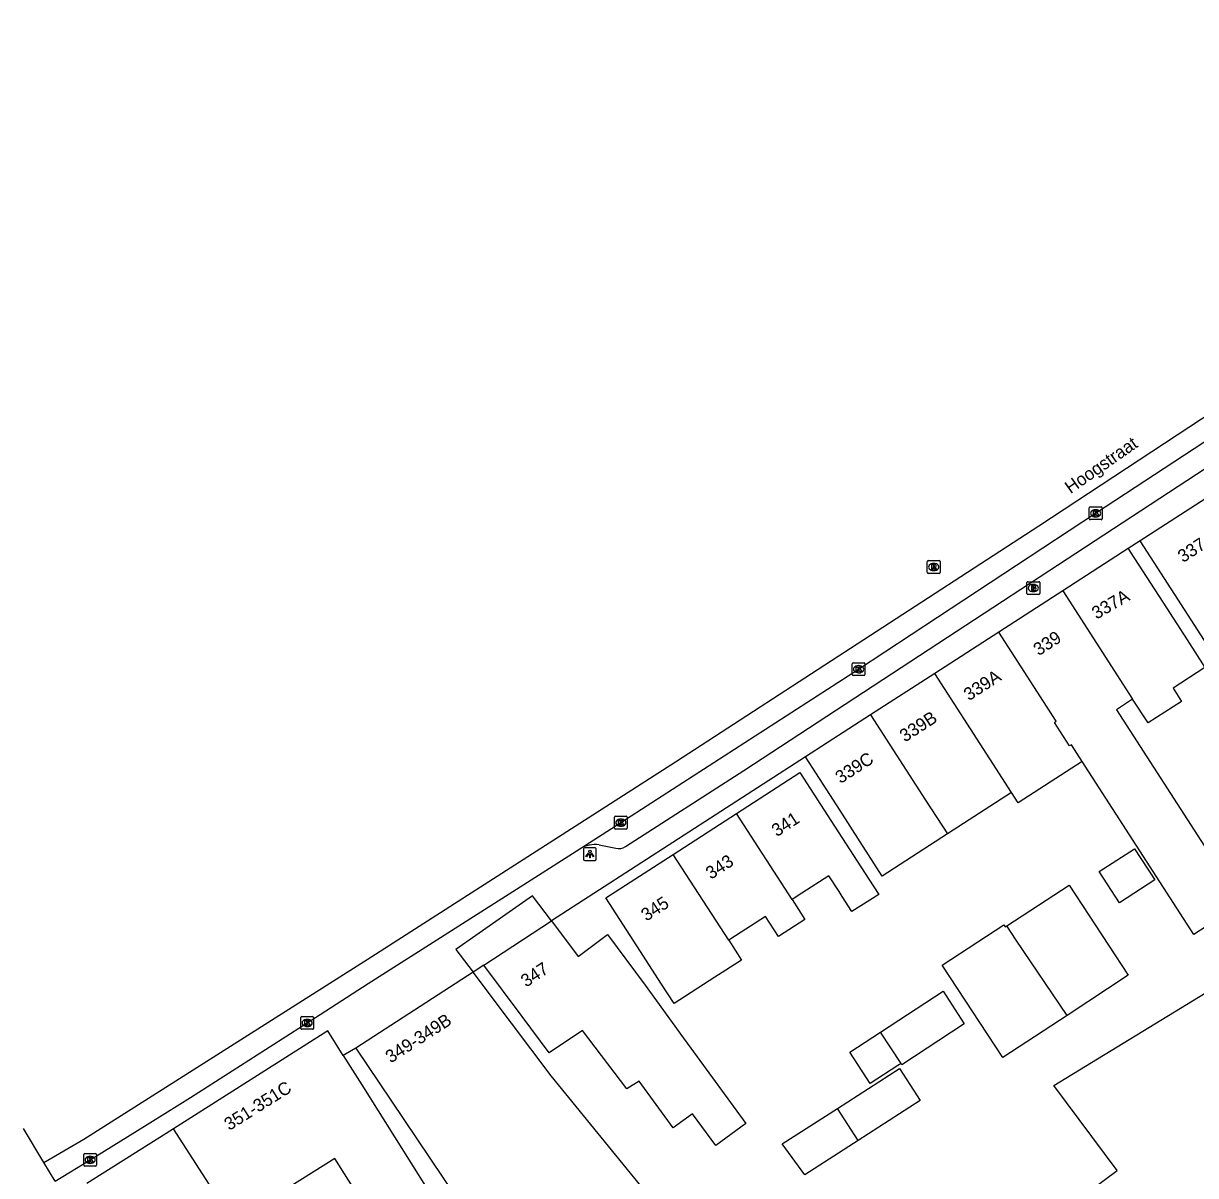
# Model space of a CAD drawing. Extents: x 159822 to 160765, y 380693 to 381634.
# Drawn here: x 160002.9 to 160094.7, y 381523.9 to 381614.2 of the extents above; entities that cross this region are included whole.
import ezdxf

# ---------------------------------------------------------------- set-up
doc = ezdxf.new("R2010")
doc.units = 0
for name, color, linetype in [('IMGEO_Brandkraan', 7, 'Continuous'), ('IMGEO_Erf', 7, 'Continuous'), ('IMGEO_Kolk', 7, 'Continuous'), ('IMGEO_Lichtpunt', 7, 'Continuous'), ('IMGEO_Openbare_ruimte_label', 7, 'Continuous'), ('IMGEO_Pand', 7, 'Continuous'), ('IMGEO_Pand_nummerreeks', 7, 'Continuous'), ('IMGEO_Rijbaan_lokaal_gesloten', 7, 'Continuous'), ('IMGEO_Rioolput', 7, 'Continuous'), ('IMGEO_Voetpad_open', 7, 'Continuous')]:
    doc.layers.add(name, color=color, linetype=linetype)

msp = doc.modelspace()

# ---------------------------------------------------------------- linework, layer by layer
at = {"layer": 'IMGEO_Brandkraan'}
for p, q in [((160081.484, 381569.508), (160081.484, 381570.36)), ((160081.559, 381570.434), (160082.411, 381570.434)), ((160081.972, 381570.214), (160081.997, 381570.214)), ((160082.485, 381570.36), (160082.485, 381569.508)), ((160082.411, 381569.434), (160081.559, 381569.434)), ((160081.995, 381569.654), (160081.97, 381569.654))]:
    msp.add_line(p, q, dxfattribs=at)
for points in [[(160081.484, 381569.508), (160081.484, 381570.36)], [(160081.559, 381570.434), (160082.411, 381570.434)], [(160081.832, 381570.134), (160081.832, 381569.734), (160082.045, 381569.734)], [(160082.063, 381570.134), (160081.832, 381570.134)], [(160082.011, 381570.053), (160081.957, 381570.053), (160081.957, 381569.977)], [(160081.957, 381569.977), (160082.01, 381569.977)], [(160082.019, 381569.901), (160081.957, 381569.901), (160081.957, 381569.82)], [(160081.957, 381569.82), (160082.019, 381569.82)], [(160082.485, 381570.36), (160082.485, 381569.508)], [(160082.411, 381569.434), (160081.559, 381569.434)]]:
    msp.add_lwpolyline(points, dxfattribs=at)
for centre, radius, start, end in [((160081.561, 381570.358), 0.0765, 91.55205, 178.44795), ((160081.561, 381570.358), 0.0765, 91.55205, 178.44795), ((160082.012, 381570.015), 0.0379, 267.82845, 90.93552), ((160082.02, 381569.86), 0.0404, 269.87594, 90.50774), ((160082.067, 381569.989), 0.145, 59.4692, 91.53667), ((160082.092, 381570.036), 0.0922, 285.51372, 58.15012), ((160082.097, 381569.844), 0.105, 301.31148, 78.98903), ((160082.409, 381570.358), 0.0765, 1.55205, 88.44795), ((160082.409, 381570.358), 0.0765, 1.55205, 88.44795), ((160081.561, 381569.51), 0.0765, 181.55205, 268.44795), ((160081.561, 381569.51), 0.0765, 181.55205, 268.44795), ((160082.051, 381569.985), 0.251, 268.66757, 293.53466), ((160082.409, 381569.51), 0.0765, 271.55205, 358.44795), ((160082.409, 381569.51), 0.0765, 271.55205, 358.44795)]:
    msp.add_arc(centre, radius, start, end, dxfattribs=at)
for centre, major_axis, ratio, start_param, end_param in [((160081.971, 381569.934), (-0.387, 0.002), 0.722429, 4.712389, 7.853982), ((160081.996, 381569.934), (-0.39, 0.002), 0.717154, 1.570796, 4.712389)]:
    msp.add_ellipse(centre, major_axis=major_axis, ratio=ratio, start_param=start_param, end_param=end_param, dxfattribs=at)
at = {"layer": 'IMGEO_Erf'}
msp.add_lwpolyline([(160038.953, 381540.37), (160038.115, 381539.825)], dxfattribs=at)
at = {"layer": 'IMGEO_Kolk'}
for p, q in [((160086.447, 381576.297), (160087.299, 381576.297)), ((160086.372, 381575.371), (160086.372, 381576.223)), ((160086.883, 381575.517), (160086.858, 381575.517)), ((160086.86, 381576.077), (160086.885, 381576.077)), ((160087.373, 381576.223), (160087.373, 381575.371)), ((160087.299, 381575.297), (160086.447, 381575.297)), ((160067.799, 381563.149), (160067.799, 381564.001)), ((160067.874, 381564.075), (160068.726, 381564.075)), ((160068.287, 381563.855), (160068.312, 381563.855)), ((160068.8, 381564.001), (160068.8, 381563.149)), ((160068.726, 381563.075), (160067.874, 381563.075)), ((160068.31, 381563.295), (160068.285, 381563.295)), ((160049.175, 381551.125), (160049.175, 381551.977)), ((160049.25, 381552.051), (160050.102, 381552.051)), ((160049.663, 381551.831), (160049.688, 381551.831)), ((160050.176, 381551.977), (160050.176, 381551.125)), ((160050.102, 381551.051), (160049.25, 381551.051)), ((160049.686, 381551.271), (160049.661, 381551.271)), ((160024.598, 381535.428), (160024.598, 381536.28)), ((160024.673, 381536.354), (160025.525, 381536.354)), ((160025.086, 381536.134), (160025.111, 381536.134)), ((160025.599, 381536.28), (160025.599, 381535.428)), ((160025.525, 381535.354), (160024.673, 381535.354)), ((160025.109, 381535.574), (160025.084, 381535.574)), ((160007.597, 381524.697), (160007.597, 381525.549)), ((160007.672, 381525.623), (160008.524, 381525.623)), ((160008.108, 381524.843), (160008.083, 381524.843)), ((160008.085, 381525.403), (160008.11, 381525.403)), ((160008.598, 381525.549), (160008.598, 381524.697)), ((160008.524, 381524.623), (160007.672, 381524.623))]:
    msp.add_line(p, q, dxfattribs=at)
for points in [[(160086.447, 381576.297), (160087.299, 381576.297)], [(160086.372, 381575.371), (160086.372, 381576.223)], [(160086.693, 381575.997), (160086.816, 381575.997), (160086.816, 381575.846), (160086.946, 381575.997), (160087.11, 381575.997), (160086.964, 381575.846), (160087.117, 381575.597), (160086.965, 381575.597), (160086.88, 381575.761), (160086.816, 381575.694), (160086.816, 381575.597), (160086.693, 381575.597), (160086.693, 381575.997)], [(160087.373, 381576.223), (160087.373, 381575.371)], [(160087.299, 381575.297), (160086.447, 381575.297)], [(160067.799, 381563.149), (160067.799, 381564.001)], [(160067.874, 381564.075), (160068.726, 381564.075)], [(160068.12, 381563.775), (160068.243, 381563.775), (160068.243, 381563.624), (160068.373, 381563.775), (160068.537, 381563.775), (160068.391, 381563.624), (160068.544, 381563.375), (160068.392, 381563.375), (160068.307, 381563.539), (160068.243, 381563.472), (160068.243, 381563.375), (160068.12, 381563.375), (160068.12, 381563.775)], [(160068.8, 381564.001), (160068.8, 381563.149)], [(160068.726, 381563.075), (160067.874, 381563.075)], [(160049.175, 381551.125), (160049.175, 381551.977)], [(160049.25, 381552.051), (160050.102, 381552.051)], [(160049.496, 381551.751), (160049.619, 381551.751), (160049.619, 381551.6), (160049.749, 381551.751), (160049.913, 381551.751), (160049.767, 381551.6), (160049.92, 381551.351), (160049.768, 381551.351), (160049.683, 381551.515), (160049.619, 381551.448), (160049.619, 381551.351), (160049.496, 381551.351), (160049.496, 381551.751)], [(160050.176, 381551.977), (160050.176, 381551.125)], [(160050.102, 381551.051), (160049.25, 381551.051)], [(160024.598, 381535.428), (160024.598, 381536.28)], [(160024.673, 381536.354), (160025.525, 381536.354)], [(160024.919, 381536.054), (160025.042, 381536.054), (160025.042, 381535.903), (160025.172, 381536.054), (160025.336, 381536.054), (160025.19, 381535.903), (160025.343, 381535.654), (160025.191, 381535.654), (160025.106, 381535.818), (160025.042, 381535.751), (160025.042, 381535.654), (160024.919, 381535.654), (160024.919, 381536.054)], [(160025.599, 381536.28), (160025.599, 381535.428)], [(160025.525, 381535.354), (160024.673, 381535.354)], [(160007.597, 381524.697), (160007.597, 381525.549)], [(160007.672, 381525.623), (160008.524, 381525.623)], [(160007.918, 381525.323), (160008.041, 381525.323), (160008.041, 381525.172), (160008.171, 381525.323), (160008.335, 381525.323), (160008.189, 381525.172), (160008.342, 381524.923), (160008.19, 381524.923), (160008.105, 381525.087), (160008.041, 381525.02), (160008.041, 381524.923), (160007.918, 381524.923), (160007.918, 381525.323)], [(160008.598, 381525.549), (160008.598, 381524.697)], [(160008.524, 381524.623), (160007.672, 381524.623)]]:
    msp.add_lwpolyline(points, dxfattribs=at)
for centre, start, end in [((160086.449, 381576.221), 91.55205, 178.44795), ((160086.449, 381576.221), 91.55205, 178.44795), ((160087.297, 381576.221), 1.55205, 88.44795), ((160087.297, 381576.221), 1.55205, 88.44795), ((160086.449, 381575.373), 181.55205, 268.44795), ((160086.449, 381575.373), 181.55205, 268.44795), ((160087.297, 381575.373), 271.55205, 358.44795), ((160087.297, 381575.373), 271.55205, 358.44795), ((160067.876, 381563.999), 91.55205, 178.44795), ((160067.876, 381563.999), 91.55205, 178.44795), ((160068.724, 381563.999), 1.55205, 88.44795), ((160068.724, 381563.999), 1.55205, 88.44795), ((160067.876, 381563.151), 181.55205, 268.44795), ((160067.876, 381563.151), 181.55205, 268.44795), ((160068.724, 381563.151), 271.55205, 358.44795), ((160068.724, 381563.151), 271.55205, 358.44795), ((160049.252, 381551.975), 91.55205, 178.44795), ((160049.252, 381551.975), 91.55205, 178.44795), ((160050.1, 381551.975), 1.55205, 88.44795), ((160050.1, 381551.975), 1.55205, 88.44795), ((160049.252, 381551.127), 181.55205, 268.44795), ((160049.252, 381551.127), 181.55205, 268.44795), ((160050.1, 381551.127), 271.55205, 358.44795), ((160050.1, 381551.127), 271.55205, 358.44795), ((160024.675, 381536.278), 91.55205, 178.44795), ((160024.675, 381536.278), 91.55205, 178.44795), ((160025.523, 381536.278), 1.55205, 88.44795), ((160025.523, 381536.278), 1.55205, 88.44795), ((160024.675, 381535.43), 181.55205, 268.44795), ((160024.675, 381535.43), 181.55205, 268.44795), ((160025.523, 381535.43), 271.55205, 358.44795), ((160025.523, 381535.43), 271.55205, 358.44795), ((160007.674, 381525.547), 91.55205, 178.44795), ((160007.674, 381525.547), 91.55205, 178.44795), ((160008.522, 381525.547), 1.55205, 88.44795), ((160008.522, 381525.547), 1.55205, 88.44795), ((160007.674, 381524.699), 181.55205, 268.44795), ((160007.674, 381524.699), 181.55205, 268.44795), ((160008.522, 381524.699), 271.55205, 358.44795), ((160008.522, 381524.699), 271.55205, 358.44795)]:
    msp.add_arc(centre, 0.0765, start, end, dxfattribs=at)
for centre, major_axis, ratio, start_param, end_param in [((160086.859, 381575.797), (-0.387, 0.002), 0.722429, 4.712389, 7.853982), ((160086.884, 381575.797), (-0.39, 0.002), 0.717154, 1.570796, 4.712389), ((160068.286, 381563.575), (-0.387, 0.002), 0.722429, 4.712389, 7.853982), ((160068.311, 381563.575), (-0.39, 0.002), 0.717154, 1.570796, 4.712389), ((160049.662, 381551.551), (-0.387, 0.002), 0.722429, 4.712389, 7.853982), ((160049.687, 381551.551), (-0.39, 0.002), 0.717154, 1.570796, 4.712389), ((160025.085, 381535.854), (-0.387, 0.002), 0.722429, 4.712389, 7.853982), ((160025.11, 381535.854), (-0.39, 0.002), 0.717154, 1.570796, 4.712389), ((160008.084, 381525.123), (-0.387, 0.002), 0.722429, 4.712389, 7.853982), ((160008.109, 381525.123), (-0.39, 0.002), 0.717154, 1.570796, 4.712389)]:
    msp.add_ellipse(centre, major_axis=major_axis, ratio=ratio, start_param=start_param, end_param=end_param, dxfattribs=at)
at = {"layer": 'IMGEO_Lichtpunt'}
for p, q in [((160046.756, 381549.491), (160046.756, 381548.684)), ((160046.756, 381549.491), (160046.756, 381548.684)), ((160047.658, 381549.586), (160046.85, 381549.586)), ((160047.658, 381549.586), (160046.85, 381549.586)), ((160047.752, 381548.684), (160047.752, 381549.491)), ((160047.752, 381548.684), (160047.752, 381549.491)), ((160046.85, 381548.59), (160047.658, 381548.59)), ((160046.85, 381548.59), (160047.658, 381548.59))]:
    msp.add_line(p, q, dxfattribs=at)
for points in [[(160047.13, 381549.155), (160047.169, 381549.127), (160046.981, 381548.865), (160046.943, 381548.892), (160047.13, 381549.155)], [(160047.232, 381549.107), (160047.279, 381549.107), (160047.279, 381548.785), (160047.232, 381548.785), (160047.232, 381549.107)], [(160047.342, 381549.127), (160047.38, 381549.154), (160047.567, 381548.892), (160047.528, 381548.864), (160047.342, 381549.127)]]:
    msp.add_lwpolyline(points, dxfattribs=at)
msp.add_circle((160047.255, 381549.289), 0.0994, dxfattribs=at)
for centre, start, end in [((160046.85, 381549.491), 90, 180), ((160046.85, 381549.491), 90, 180), ((160046.85, 381548.684), 180, 270), ((160046.85, 381548.684), 180, 270), ((160047.658, 381549.491), 0, 90), ((160047.658, 381549.491), 0, 90), ((160047.658, 381548.684), 270, 0), ((160047.658, 381548.684), 270, 360)]:
    msp.add_arc(centre, 0.0946, start, end, dxfattribs=at)
at = {"layer": 'IMGEO_Pand'}
for points in [[(160095.508, 381576.952), (160090.358, 381573.626)], [(160111.401, 381551.466), (160106.639, 381548.393), (160093.069, 381569.425), (160090.358, 381573.626)], [(160089.426, 381573.024), (160084.293, 381569.71)], [(160089.426, 381573.024), (160089.58, 381572.786), (160092.139, 381568.82), (160094.029, 381565.891), (160095.435, 381563.711), (160092.933, 381562.096), (160093.607, 381561.052), (160090.99, 381559.363), (160089.77, 381561.223)], [(160084.293, 381569.71), (160079.277, 381566.473)], [(160084.293, 381569.71), (160089.77, 381561.223)], [(160079.277, 381566.473), (160074.26, 381563.234)], [(160085.817, 381556.338), (160084.969, 381557.652), (160084.834, 381557.564), (160083.644, 381559.407), (160083.78, 381559.495), (160079.277, 381566.473)], [(160074.26, 381563.234), (160069.245, 381559.997)], [(160080.28, 381553.904), (160078.579, 381556.541), (160074.26, 381563.234)], [(160089.77, 381561.223), (160088.494, 381560.4), (160098.296, 381545.21), (160094.556, 381542.797), (160085.817, 381556.338)], [(160069.245, 381559.997), (160064.133, 381556.697)], [(160069.245, 381559.997), (160073.551, 381553.324), (160075.265, 381550.666)], [(160075.265, 381550.666), (160070.155, 381547.367), (160068.423, 381550.05), (160066.845, 381552.496), (160064.133, 381556.697)], [(160085.817, 381556.338), (160080.8, 381553.099), (160080.28, 381553.904)], [(160058.738, 381552.271), (160063.706, 381555.488), (160066.417, 381551.287), (160069.104, 381547.123), (160069.874, 381545.93), (160067.781, 381544.579), (160067.011, 381545.772), (160066.772, 381546.143), (160065.968, 381547.388), (160063.846, 381546.019), (160063.182, 381545.591), (160063.088, 381545.53)], [(160080.28, 381553.904), (160075.265, 381550.666)], [(160053.785, 381549.064), (160058.738, 381552.271)], [(160063.088, 381545.53), (160058.738, 381552.271)], [(160058.124, 381542.342), (160059.129, 381540.785), (160057.044, 381539.44), (160053.848, 381537.377), (160052.819, 381538.971), (160051.221, 381541.447), (160048.51, 381545.648), (160053.785, 381549.064)], [(160058.124, 381542.342), (160053.785, 381549.064)], [(160087.155, 381547.723), (160089.916, 381549.505), (160091.496, 381547.056), (160088.735, 381545.274), (160087.155, 381547.723)], [(160079.918, 381543.458), (160084.79, 381546.655), (160089.429, 381539.588), (160084.634, 381536.441)], [(160063.088, 381545.53), (160064.097, 381543.967), (160062.026, 381542.63), (160061.01, 381544.205), (160058.291, 381542.45), (160058.124, 381542.342)], [(160044.254, 381543.855), (160046.328, 381541.069), (160048.636, 381542.793), (160051.59, 381538.802), (160054.594, 381534.655), (160055.146, 381533.881), (160059.463, 381527.971), (160057.11, 381526.252), (160055.3, 381528.73), (160053.782, 381527.621), (160051.102, 381531.29), (160050.142, 381530.675), (160046.669, 381535.268), (160044.068, 381533.505), (160041.94, 381536.361), (160038.953, 381540.37)], [(160038.953, 381540.37), (160044.254, 381543.855)], [(160084.634, 381536.441), (160079.609, 381533.144), (160074.858, 381540.383), (160079.681, 381543.549), (160079.794, 381543.377), (160079.918, 381543.458)], [(160084.634, 381536.441), (160080.647, 381542.328), (160079.918, 381543.458)], [(160110.69, 381494.11), (160105.284, 381501.642), (160102.69, 381505.019), (160102.11, 381505.796), (160097.351, 381512.166), (160089.073, 381505.982), (160080.102, 381517.993), (160088.554, 381524.298), (160083.587, 381530.947), (160101.421, 381541.836)], [(160038.115, 381539.825), (160028.91, 381533.878)], [(160028.91, 381533.878), (160031.703, 381529.731), (160036.757, 381522.228), (160037.103, 381522.461), (160046.627, 381508.396), (160053.016, 381512.481), (160052.51, 381513.232), (160056.874, 381516.17), (160044.202, 381531.699), (160041.112, 381535.824), (160038.115, 381539.825)], [(160070.013, 381535.137), (160074.917, 381538.355), (160076.58, 381535.783), (160071.694, 381532.576), (160071.63, 381532.673)], [(160027.93, 381533.3), (160026.718, 381535.224), (160014.641, 381527.565)], [(160071.63, 381532.673), (160071.373, 381532.507), (160069.208, 381531.113), (160067.604, 381533.556), (160070.013, 381535.137)], [(160071.63, 381532.673), (160070.013, 381535.137)], [(160027.93, 381533.3), (160029.382, 381530.994), (160035.788, 381520.822), (160031.683, 381518.237), (160027.275, 381525.235), (160021.998, 381521.911), (160024.38, 381518.196), (160025.929, 381519.252), (160036.236, 381503.697), (160034.773, 381502.7)], [(160066.636, 381529.156), (160071.51, 381532.294), (160073.13, 381529.778), (160068.26, 381526.642)], [(160068.26, 381526.642), (160064.076, 381523.949), (160062.322, 381526.379), (160066.636, 381529.156)], [(160068.26, 381526.642), (160066.636, 381529.156)], [(160014.641, 381527.565), (160014.041, 381527.185), (160007.851, 381523.273)], [(160019.688, 381519.696), (160014.641, 381527.565)]]:
    msp.add_lwpolyline(points, dxfattribs=at)
at = {"layer": 'IMGEO_Rijbaan_lokaal_gesloten'}
for points in [[(160004.479, 381524.903), (160007.612, 381526.743), (160029.796, 381540.829), (160053.944, 381556.307), (160082.43, 381574.817), (160112.881, 381594.842), (160137.027, 381611.139), (160140.076, 381613.062), (160141.863, 381614.189)], [(160046.466, 381549.511), (160049.671, 381551.552), (160068.295, 381563.576), (160086.868, 381575.798), (160104.583, 381587.419), (160119.163, 381597.14), (160122.767, 381599.539)], [(160005.352, 381523.447), (160008.094, 381525.124), (160011.607, 381527.279), (160015.114, 381529.478), (160015.964, 381530.015), (160025.094, 381535.855), (160026.107, 381536.518), (160029.867, 381538.931), (160042.646, 381547.078), (160046.466, 381549.511)], [(160004.479, 381524.903), (160002.872, 381527.582)], [(160005.352, 381523.447), (160004.479, 381524.903)]]:
    msp.add_lwpolyline(points, dxfattribs=at)
at = {"layer": 'IMGEO_Rioolput'}
for p, q in [((160073.684, 381571.158), (160073.684, 381572.01)), ((160073.759, 381572.084), (160074.611, 381572.084)), ((160074.172, 381571.864), (160074.197, 381571.864)), ((160074.685, 381572.01), (160074.685, 381571.158)), ((160074.611, 381571.084), (160073.759, 381571.084)), ((160074.195, 381571.304), (160074.17, 381571.304))]:
    msp.add_line(p, q, dxfattribs=at)
for points in [[(160073.684, 381571.158), (160073.684, 381572.01)], [(160073.759, 381572.084), (160074.611, 381572.084)], [(160074.273, 381571.782), (160074.021, 381571.784), (160074.021, 381571.384)], [(160074.199, 381571.703), (160074.145, 381571.703), (160074.145, 381571.622)], [(160074.685, 381572.01), (160074.685, 381571.158)], [(160074.611, 381571.084), (160073.759, 381571.084)], [(160074.021, 381571.384), (160074.145, 381571.384), (160074.145, 381571.546), (160074.156, 381571.546)], [(160074.145, 381571.622), (160074.197, 381571.622)], [(160074.203, 381571.517), (160074.274, 381571.384), (160074.414, 381571.384), (160074.349, 381571.51)]]:
    msp.add_lwpolyline(points, dxfattribs=at)
for centre, radius, start, end in [((160073.761, 381572.008), 0.0765, 91.55205, 178.44795), ((160073.761, 381572.008), 0.0765, 91.55205, 178.44795), ((160074.205, 381571.607), 0.0964, 77.00612, 93.18647), ((160074.219, 381571.664), 0.0378, 276.66336, 79.67722), ((160074.272, 381571.672), 0.109, 350.36119, 89.41601), ((160074.27, 381571.672), 0.112, 277.58423, 350.98172), ((160074.609, 381572.008), 0.0765, 1.55205, 88.44795), ((160074.609, 381572.008), 0.0765, 1.55205, 88.44795), ((160073.761, 381571.16), 0.0765, 181.55205, 268.44795), ((160073.761, 381571.16), 0.0765, 181.55205, 268.44795), ((160074.155, 381571.493), 0.0533, 26.02933, 88.69889), ((160074.181, 381571.811), 0.19, 274.7715, 282.96867), ((160074.254, 381571.457), 0.108, 29.51342, 73.79051), ((160074.609, 381571.16), 0.0765, 271.55205, 358.44795), ((160074.609, 381571.16), 0.0765, 271.55205, 358.44795)]:
    msp.add_arc(centre, radius, start, end, dxfattribs=at)
for centre, major_axis, ratio, start_param, end_param in [((160074.171, 381571.584), (-0.387, 0.002), 0.722429, 4.712389, 7.853982), ((160074.196, 381571.584), (-0.39, 0.002), 0.717154, 1.570796, 4.712389)]:
    msp.add_ellipse(centre, major_axis=major_axis, ratio=ratio, start_param=start_param, end_param=end_param, dxfattribs=at)
at = {"layer": 'IMGEO_Voetpad_open'}
for points in [[(160050.028, 381549.673), (160059.297, 381555.627), (160101.271, 381583.115), (160104.638, 381585.323), (160113.384, 381591.146), (160120.932, 381596.202), (160121.34, 381596.46)], [(160090.358, 381573.626), (160089.426, 381573.024)], [(160064.133, 381556.697), (160044.254, 381543.855)], [(160047.983, 381549.812), (160049.272, 381549.55)], [(160044.254, 381543.855), (160042.75, 381545.811), (160036.759, 381541.611), (160038.115, 381539.825)], [(160028.91, 381533.878), (160027.93, 381533.3)]]:
    msp.add_lwpolyline(points, dxfattribs=at)
for centre, radius, start, end in [((160047.649, 381547.521), 2.315, 81.70943, 120.73607), ((160049.508, 381550.482), 0.961, 255.76651, 302.71541)]:
    msp.add_arc(centre, radius, start, end, dxfattribs=at)

# ---------------------------------------------------------------- texts
at = {"layer": 'IMGEO_Openbare_ruimte_label'}
msp.add_text('Hoogstraat', height=1, rotation=35.02487, dxfattribs=at).set_placement((160084.903, 381577.287))
at = {"layer": 'IMGEO_Pand_nummerreeks'}
for s, rotation, p in [('337', 32.84333, (160093.715, 381571.89)), ('337A', 30.18915, (160086.937, 381567.453)), ('339', 32.83557, (160082.405, 381564.589)), ('339A', 32.84767, (160076.945, 381561.064)), ('339B', 32.84194, (160071.929, 381557.826)), ('339C', 32.84386, (160066.886, 381554.571)), ('341', 32.92215, (160061.895, 381550.407)), ('343', 32.92215, (160056.734, 381547.066)), ('345', 32.92215, (160051.669, 381543.786)), ('347', 33.32184, (160042.254, 381538.615)), ('349-349B', 32.86486, (160031.646, 381532.669)), ('351-351C', 32.18304, (160019, 381527.385))]:
    msp.add_text(s, height=1, rotation=rotation, dxfattribs=at).set_placement(p)

doc.saveas('drawing.dxf')
